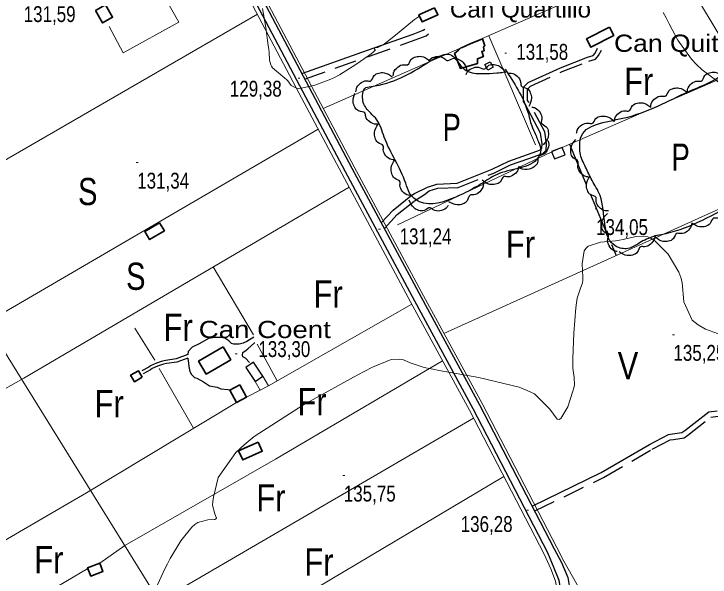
# Model space of a CAD drawing. Extents: x 487425 to 492029, y 4383576 to 4386788.
# Drawn here: x 490517.3 to 490901.3, y 4385154.5 to 4385465.2 of the extents above; entities that cross this region are included whole.
import ezdxf
from ezdxf.enums import TextEntityAlignment as Align

# ---------------------------------------------------------------- set-up
doc = ezdxf.new("R2010")
doc.units = 0
doc.header["$LTSCALE"] = 4
doc.linetypes.add('LONG_DASHED', pattern=[7.5, 6, -1.5])
doc.linetypes.add('MEDIUM_DASHED', pattern=[4.5, 3, -1.5])
for name, color, linetype, lineweight in [('21', 7, 'Continuous', 25), ('25', 7, 'LONG_DASHED', 25), ('27', 7, 'Continuous', 25), ('36', 7, 'Continuous', 25), ('38', 7, 'Continuous', 25), ('47', 7, 'Continuous', 35), ('48', 7, 'MEDIUM_DASHED', 25), ('51', 7, 'Continuous', 13), ('7', 7, 'Continuous', 13), ('9', 7, 'Continuous', 13)]:
    doc.layers.add(name, color=color, linetype=linetype, lineweight=lineweight)
doc.layers.add('31', color=7, linetype='Continuous')
doc.layers.add('5', color=7, linetype='Continuous')

msp = doc.modelspace()

# ---------------------------------------------------------------- linework, layer by layer
at = {"layer": '21'}
for points in [[(490777.11, 4385437.26), (490779.99, 4385438.8), (490781.6, 4385435.75), (490778.72, 4385434.21)], [(490645.16, 4385270.16), (490650.38, 4385262.38), (490654.67, 4385265.26), (490649.45, 4385273.04)]]:
    msp.add_lwpolyline(points, close=True, dxfattribs=at)
at = {"layer": '25'}
msp.add_line((490823.76, 4385393.3), (490849.42, 4385331.9), dxfattribs=at)
at = {"layer": '27'}
for points in [[(490788.2, 4385434.68), (490800.8, 4385410.95), (490802.95, 4385403.52), (490805.03, 4385398.72), (490806.15, 4385395.79), (490807.86, 4385390.98), (490807.17, 4385387.24), (490784.95, 4385377.11), (490776.31, 4385372.26), (490766.4, 4385366.67), (490760.99, 4385364.13), (490741.11, 4385361.57), (490735.58, 4385366.31), (490733.42, 4385371.79), (490721.58, 4385397.17), (490717.41, 4385406.85), (490714.12, 4385410.46), (490710.01, 4385416.25), (490709.65, 4385420.15), (490710.78, 4385424.12), (490714.31, 4385425.16), (490745.02, 4385438.04), (490754.48, 4385442.73), (490756.95, 4385443.02), (490762.71, 4385437.98), (490766.82, 4385434), (490775.97, 4385432.24), (490783.62, 4385432.67), (490787.44, 4385433.03)], [(490726.53, 4385431.01), (490726.76, 4385432.77), (490728.99, 4385435.83), (490732.43, 4385437.18), (490734.48, 4385437.1), (490736.43, 4385440.08), (490739.05, 4385441.52), (490742.06, 4385441.74), (490746.49, 4385439.51)], [(490746.1, 4385439.3), (490747.34, 4385440.58), (490750.96, 4385441.7), (490754.52, 4385440.73), (490756.13, 4385439.45), (490759.47, 4385440.67), (490762.42, 4385440.27), (490764.98, 4385438.64), (490767.2, 4385434.2)], [(490766.79, 4385431.84), (490767.62, 4385433.41), (490770.79, 4385435.49), (490774.48, 4385435.54), (490776.38, 4385434.75), (490779.25, 4385436.85), (490782.21, 4385437.28), (490785.11, 4385436.42), (490788.47, 4385432.78)], [(490705.93, 4385422.18), (490706.18, 4385423.94), (490708.45, 4385426.97), (490711.9, 4385428.28), (490713.96, 4385428.18), (490715.94, 4385431.13), (490718.57, 4385432.54), (490721.59, 4385432.73), (490725.99, 4385430.45)], [(490789.83, 4385432.5), (490791.6, 4385432.54), (490794.97, 4385430.79), (490796.82, 4385427.6), (490797.06, 4385425.56), (490800.3, 4385424.08), (490802.12, 4385421.72), (490802.79, 4385418.77), (490801.26, 4385414.05)], [(490949.83, 4385378.18), (490913.56, 4385359.92), (490874.3, 4385343.32), (490869.57, 4385342.21), (490868.29, 4385341.69), (490864.31, 4385339.98), (490860.41, 4385337.59), (490855.9, 4385335.73), (490849.46, 4385336.95), (490840.62, 4385365.02), (490836.22, 4385373.28), (490832.65, 4385380.64), (490829.6, 4385388.59), (490829.38, 4385392.12), (490829.84, 4385396.62), (490853.2, 4385407.64), (490889.68, 4385422.45), (490901.09, 4385427.52), (490906.95, 4385430.72), (490910.03, 4385432.21), (490917.08, 4385432.34), (490922.9, 4385424.38), (490931.03, 4385409.36), (490939.76, 4385395.98), (490943.49, 4385388.85), (490943.62, 4385381.58), (490945.7, 4385377)], [(490888.75, 4385421.84), (490888.93, 4385423.61), (490891.08, 4385426.73), (490894.48, 4385428.18), (490896.53, 4385428.16), (490898.39, 4385431.19), (490900.97, 4385432.7), (490903.98, 4385433.01), (490908.47, 4385430.9)], [(490718.85, 4385404.53), (490717.1, 4385404.28), (490713.55, 4385405.62), (490711.33, 4385408.57), (490710.85, 4385410.57), (490707.46, 4385411.65), (490705.37, 4385413.78), (490704.35, 4385416.63), (490705.32, 4385421.49)], [(490868.58, 4385413.82), (490868.83, 4385415.57), (490871.11, 4385418.6), (490874.57, 4385419.9), (490876.62, 4385419.8), (490878.62, 4385422.74), (490881.25, 4385424.15), (490884.27, 4385424.32), (490888.67, 4385422.02)], [(490552.62, 4384941.58), (490554.42, 4384943.67), (490554.9, 4384950.57), (490551.02, 4384958.75), (490549.23, 4384963.11), (490546.55, 4384969.04), (490546.27, 4384975.56), (490577.59, 4384991.51), (490608.31, 4385010.39), (490640.99, 4385029.26), (490675.61, 4385047.83), (490715.19, 4385070.58), (490756.65, 4385095.72), (490790.53, 4385116.54), (490822.22, 4385132.71), (490831.7, 4385141.3), (490834.32, 4385140.92), (490836.94, 4385139.04), (490838.42, 4385134.39), (490839.83, 4385127.26), (490841.17, 4385124.33), (490843.93, 4385120.95), (490854.88, 4385120.69), (490881, 4385131.56), (490910.74, 4385145.49), (490944, 4385160.61), (490977.26, 4385174.31), (491011.8, 4385191.9), (491038.91, 4385205.09), (491047.85, 4385210.16), (491048.16, 4385215.03), (491046.15, 4385220.51), (491027.8, 4385249.96), (491013.09, 4385271.3), (490994.07, 4385304.34), (490984.67, 4385319.67), (490979.29, 4385327.18), (490976.61, 4385330.57), (490974.75, 4385335.52), (490975.45, 4385343.54), (490977.85, 4385344.21), (490979.42, 4385344.13), (490980.47, 4385343.6), (490983.46, 4385341.64), (490988.77, 4385336.68), (490990.42, 4385334.95), (490993.78, 4385332.31), (491019.1, 4385348.81), (491045.47, 4385366.05), (491074.68, 4385380.36), (491106.91, 4385400.5), (491123.13, 4385410.28), (491127.87, 4385413.64), (491130.35, 4385415.43), (491144.45, 4385391.54), (491161.89, 4385359.02), (491165.47, 4385353.38)], [(490803.07, 4385413.77), (490804.8, 4385413.34), (490807.58, 4385410.77), (490808.52, 4385407.2), (490808.22, 4385405.17), (490810.94, 4385402.89), (490812.07, 4385400.12), (490811.94, 4385397.1), (490809.22, 4385392.96)], [(490848.44, 4385405.72), (490848.71, 4385407.48), (490851.01, 4385410.5), (490854.47, 4385411.77), (490856.52, 4385411.66), (490858.53, 4385414.6), (490861.17, 4385415.98), (490864.19, 4385416.14), (490868.58, 4385413.82)], [(490827.68, 4385399.38), (490828.06, 4385401.11), (490830.57, 4385403.96), (490834.11, 4385404.99), (490836.15, 4385404.74), (490838.36, 4385407.52), (490841.09, 4385408.72), (490844.11, 4385408.67), (490848.33, 4385406.05)], [(490727.43, 4385384.62), (490725.66, 4385384.79), (490722.53, 4385386.93), (490721.07, 4385390.32), (490721.07, 4385392.37), (490718.03, 4385394.22), (490716.51, 4385396.79), (490716.19, 4385399.79), (490718.27, 4385404.29)], [(490811.82, 4385395.38), (490812.29, 4385393.67), (490811.4, 4385389.98), (490808.74, 4385387.42), (490806.82, 4385386.69), (490806.16, 4385383.2), (490804.3, 4385380.87), (490801.6, 4385379.5), (490796.65, 4385379.86)], [(490834.03, 4385375.25), (490832.29, 4385375.62), (490829.42, 4385378.1), (490828.36, 4385381.64), (490828.61, 4385383.68), (490825.8, 4385385.87), (490824.58, 4385388.59), (490824.61, 4385391.62), (490827.2, 4385395.85)], [(490736.61, 4385364.96), (490734.84, 4385365.13), (490731.7, 4385367.26), (490730.24, 4385370.65), (490730.25, 4385372.7), (490727.21, 4385374.55), (490725.68, 4385377.12), (490725.36, 4385380.12), (490727.44, 4385384.63)], [(490795.79, 4385381.26), (490795.5, 4385379.51), (490793.14, 4385376.53), (490789.66, 4385375.31), (490787.61, 4385375.46), (490785.55, 4385372.56), (490782.88, 4385371.22), (490779.86, 4385371.12), (490775.52, 4385373.51)], [(490845.22, 4385356.48), (490843.44, 4385356.55), (490840.19, 4385358.5), (490838.54, 4385361.8), (490838.42, 4385363.85), (490835.28, 4385365.53), (490833.61, 4385368), (490833.12, 4385370.98), (490834.94, 4385375.59)], [(490776.15, 4385372.17), (490776.12, 4385370.39), (490774.23, 4385367.1), (490770.96, 4385365.39), (490768.91, 4385365.23), (490767.3, 4385362.06), (490764.86, 4385360.34), (490761.89, 4385359.79), (490757.24, 4385361.51)], [(490756.84, 4385359.42), (490755.74, 4385358.02), (490752.24, 4385356.54), (490748.6, 4385357.15), (490746.88, 4385358.27), (490743.68, 4385356.72), (490740.69, 4385356.82), (490737.99, 4385358.18), (490735.34, 4385362.37)], [(490911.02, 4385358.77), (490910.83, 4385357.01), (490908.66, 4385353.9), (490905.25, 4385352.48), (490903.2, 4385352.5), (490901.31, 4385349.49), (490898.73, 4385347.99), (490895.72, 4385347.71), (490891.24, 4385349.84)], [(490850.07, 4385334.07), (490848.36, 4385334.56), (490845.67, 4385337.24), (490844.86, 4385340.84), (490845.24, 4385342.86), (490842.59, 4385345.23), (490841.56, 4385348.04), (490841.8, 4385351.05), (490844.67, 4385355.09)], [(490891.18, 4385349.98), (490890.91, 4385348.22), (490888.59, 4385345.22), (490885.11, 4385343.97), (490883.06, 4385344.1), (490881.03, 4385341.18), (490878.38, 4385339.81), (490875.36, 4385339.67), (490870.99, 4385342.03)], [(490870.79, 4385343.09), (490870.62, 4385341.32), (490868.48, 4385338.19), (490865.08, 4385336.74), (490863.03, 4385336.75), (490861.17, 4385333.71), (490858.61, 4385332.19), (490855.6, 4385331.87), (490851.1, 4385333.97)]]:
    msp.add_spline(points, degree=3, dxfattribs=at)
at = {"layer": '36'}
for points in [[(490586.03, 4385620.72), (490604.02, 4385576.99), (490607.93, 4385561.76), (490612.84, 4385552.24), (490618.34, 4385540.93), (490627.43, 4385524.13), (490649.58, 4385482.52), (490680.08, 4385424.55), (490703.71, 4385380.18), (490741.89, 4385308.92), (490774.19, 4385249.5), (490815.35, 4385170.05), (490819.37, 4385162.64)], [(490582.19, 4385619.14), (490600.07, 4385575.67), (490604.03, 4385560.27), (490609.13, 4385550.38), (490614.65, 4385539.03), (490623.77, 4385522.17), (490645.91, 4385480.58), (490676.41, 4385422.61), (490700.04, 4385378.22), (490738.24, 4385306.94), (490770.52, 4385247.56), (490811.68, 4385168.11), (490815.13, 4385159.68)], [(490819.37, 4385162.64), (490822.86, 4385154.19), (490823.92, 4385147.66), (490822.4, 4385143.3), (490819.81, 4385139.49), (490816.13, 4385135.82), (490810.5, 4385130.98)], [(490815.13, 4385159.68), (490817.83, 4385152.81), (490818.6, 4385148.13), (490817.73, 4385145.64), (490815.81, 4385142.81), (490812.96, 4385139.97), (490809.95, 4385138.25)]]:
    msp.add_lwpolyline(points, dxfattribs=at)
at = {"layer": '38'}
for points in [[(490676.02, 4385432.26), (490712.41, 4385445.14), (490737.53, 4385453.98), (490743.05, 4385456.14), (490744.04, 4385456.85)], [(490738.18, 4385366.1), (490745.52, 4385369.68), (490750.65, 4385371.35), (490761.8, 4385371.76), (490781.07, 4385379.54), (490790.32, 4385384.01), (490800.55, 4385387.66), (490803.18, 4385388.63), (490807.72, 4385390.23), (490808.57, 4385391.06), (490808.77, 4385393.51), (490807.84, 4385399.44), (490799.32, 4385415.34), (490798.35, 4385416.79), (490798.3, 4385424.74), (490800.92, 4385427.35), (490818.74, 4385435.51), (490833.63, 4385441.25), (490836.81, 4385442.32), (490837.88, 4385443.52), (490839.28, 4385446.24)], [(490719.88, 4385349.92), (490726.42, 4385356.99), (490736.27, 4385364.82), (490738.18, 4385366.1)], [(490649.56, 4385286.94), (490645.81, 4385284.55), (490643.7, 4385283.58), (490641.53, 4385283.07), (490640.18, 4385282.99), (490638.53, 4385283), (490637.4, 4385283.3), (490635.83, 4385284.88), (490633.14, 4385286.62), (490630.52, 4385286.77), (490628.12, 4385286.71), (490624.67, 4385286.04), (490619.78, 4385283.36), (490615.58, 4385281.34), (490613.4, 4385278.95), (490613.19, 4385277.22)], [(490647.27, 4385272.93), (490644.95, 4385275.26), (490643.61, 4385276.09), (490643.38, 4385276.99), (490643.61, 4385278.41), (490645.49, 4385279.68), (490646.39, 4385280.35), (490650, 4385283.71), (490650.23, 4385283.79)], [(490613.19, 4385277.22), (490606.75, 4385274.86), (490601.1, 4385273.99), (490599.32, 4385273.6), (490595.96, 4385272.47), (490592.7, 4385271.09), (490591.7, 4385270.39), (490587.83, 4385268.25)], [(490613.16, 4385275.34), (490613.16, 4385275.13), (490613.53, 4385272.5), (490613.75, 4385270.63), (490614.34, 4385267.85), (490615.31, 4385266.35), (490616.95, 4385264.62), (490618.23, 4385264.24), (490621.82, 4385262.13), (490625.19, 4385259.95), (490629.46, 4385259.26), (490631.48, 4385258.43), (490635.23, 4385258.04), (490636.58, 4385257.66)], [(490803.25, 4385193.69), (490841.17, 4385212.14), (490867.89, 4385227.65), (490878.43, 4385233.11), (490880.62, 4385233.46), (490885.81, 4385234.27), (490887.34, 4385235.32), (490900.56, 4385245.62), (490905.29, 4385246.28)]]:
    msp.add_lwpolyline(points, dxfattribs=at)
at = {"layer": '38', "linetype": 'MEDIUM_DASHED'}
for points in [[(490677.61, 4385429.24), (490713.53, 4385441.96), (490738.7, 4385450.82), (490744.68, 4385453.16), (490746.01, 4385454.13)], [(490746.44, 4385367.52), (490751.06, 4385369.02), (490762.3, 4385369.43), (490782.02, 4385377.4), (490791.23, 4385381.85), (490801.34, 4385385.46), (490803.97, 4385386.43), (490808.99, 4385388.19), (490810.83, 4385390), (490811.13, 4385393.6), (490810.09, 4385400.2), (490801.33, 4385416.54), (490800.69, 4385417.51), (490800.64, 4385423.77), (490802.28, 4385425.39), (490819.65, 4385433.35), (490834.42, 4385439.05), (490838.14, 4385440.3), (490839.83, 4385442.18), (490841.37, 4385445.16)], [(490721.63, 4385346.73), (490728.77, 4385354.45), (490738.3, 4385362.03), (490743.72, 4385365.64), (490746.44, 4385367.52)], [(490613.16, 4385275.34), (490607.19, 4385273.15), (490601.42, 4385272.26), (490599.79, 4385271.91), (490596.58, 4385270.83), (490593.56, 4385269.55), (490592.63, 4385268.9), (490588.67, 4385266.72)], [(490804.57, 4385190.98), (490842.59, 4385209.48), (490869.34, 4385225), (490879.39, 4385230.21), (490881.09, 4385230.48), (490886.96, 4385231.4), (490889.13, 4385232.89), (490901.78, 4385242.74), (490905.71, 4385243.3)]]:
    msp.add_lwpolyline(points, dxfattribs=at)
at = {"layer": '38', "linetype": 'LONG_DASHED'}
msp.add_spline([(490856.41, 4385107.49), (490859.65, 4385110.18), (490867.38, 4385114.43), (490873.91, 4385115.53), (490887.03, 4385114.37), (490896.55, 4385115.32), (490924.27, 4385131.13), (490927.87, 4385133.82), (490941.1, 4385145.17), (490947.19, 4385149.8), (490963.04, 4385157.48), (490967.84, 4385158.06), (490984.27, 4385160.94), (490997.92, 4385161.95), (491003.62, 4385163.35), (491033.48, 4385171.21), (491039.72, 4385174.94), (491044.16, 4385180.85), (491046.74, 4385189.62), (491047.5, 4385195.54), (491053.9, 4385202.57), (491077.72, 4385221.09), (491118.14, 4385248.18), (491145.63, 4385263.7), (491161.54, 4385265.75), (491194.04, 4385279.67), (491203.47, 4385287.37)], degree=3, dxfattribs=at)
at = {"layer": '47'}
for points in [[(490562.3, 4385467.01), (490566.18, 4385460.24), (490571.67, 4385463.38), (490567.79, 4385470.15)], [(490749.38, 4385468.61), (490740.69, 4385464.68), (490742.46, 4385460.76), (490751.15, 4385464.69)], [(490845.85, 4385457.83), (490833.22, 4385451.37), (490835.54, 4385446.84), (490848.17, 4385453.3)], [(490775.72, 4385451.37), (490768.89, 4385448.76), (490764.16, 4385446.53), (490763.94, 4385446.6), (490762.51, 4385445.26), (490760.4, 4385443.39), (490763.6, 4385435.13), (490772.98, 4385437.8), (490772.99, 4385440.5), (490776.3, 4385441.69), (490775.4, 4385444.54), (490776.68, 4385444.91), (490776.31, 4385446.86), (490776.69, 4385447.31), (490776.99, 4385447.61)], [(490597.64, 4385350.01), (490589.5, 4385345.12), (490592.14, 4385340.72), (490600.28, 4385345.61)], [(490632.67, 4385281.59), (490619.13, 4385273.63), (490623.33, 4385266.48), (490636.87, 4385274.44)], [(490588.09, 4385264.78), (490583.72, 4385262.25), (490581.64, 4385265.85), (490586.01, 4385268.38)], [(490641.98, 4385260.65), (490645.66, 4385253.84), (490640.08, 4385250.83), (490636.4, 4385257.64)], [(490652.01, 4385228.97), (490641.25, 4385224.15), (490643.51, 4385219.1), (490654.27, 4385223.92)], [(490564.61, 4385162.21), (490557.91, 4385159.69), (490559.64, 4385155.1), (490566.34, 4385157.62)]]:
    msp.add_lwpolyline(points, close=True, dxfattribs=at)
at = {"layer": '48'}
msp.add_lwpolyline([(490819.71, 4385391.55), (490813.9, 4385389.31), (490815.49, 4385385.19), (490821.3, 4385387.43)], close=True, dxfattribs=at)
at = {"layer": '51'}
for p, q in [((490651.65, 4385465), (490463.33, 4385356.18)), ((490779.27, 4385453.14), (490805.09, 4385393.02)), ((490754.5, 4385288.95), (490942.62, 4385374.08)), ((490627.18, 4385325.58), (490649.42, 4385288.07)), ((490584.04, 4385291.86), (490595.01, 4385274.13)), ((490651.5, 4385282.96), (490662.52, 4385262.72)), ((490597.47, 4385269.63), (490616.4, 4385236.6)), ((490654.67, 4385265.26), (490657.73, 4385260)), ((490653.15, 4385257.69), (490645.55, 4385253.79))]:
    msp.add_line(p, q, dxfattribs=at)
for points in [[(490770.28, 4385676.52), (490879.71, 4385498.21), (490946.11, 4385387.72), (490972.53, 4385346.55), (491015.95, 4385275.04), (491056.79, 4385212.45)], [(490587.46, 4385621.31), (490605.49, 4385577.48), (490609.38, 4385562.31), (490614.22, 4385552.93), (490619.71, 4385541.63), (490628.79, 4385524.86), (490650.94, 4385483.24), (490681.44, 4385425.27), (490705.07, 4385380.91), (490743.25, 4385309.65), (490775.55, 4385250.22), (490816.71, 4385170.77), (490820.72, 4385163.37)], [(490580.18, 4385618.32), (490598, 4385574.99), (490601.98, 4385559.5), (490607.19, 4385549.41), (490612.71, 4385538.04), (490621.86, 4385521.14), (490643.99, 4385479.56), (490674.49, 4385421.59), (490698.13, 4385377.2), (490736.33, 4385305.92), (490768.6, 4385246.54), (490809.76, 4385167.09), (490813.48, 4385159.03)], [(490313.87, 4385607.89), (490313.11, 4385605.12), (490313.1, 4385601.75), (490319.28, 4385587.48), (490405.61, 4385447.53), (490502.62, 4385293.98), (490596.94, 4385142.16), (490654.78, 4385048.84)], [(490687.94, 4385413.08), (490781.51, 4385454.12), (490880.25, 4385497.32)], [(490569.78, 4385458.21), (490577.53, 4385443.79), (490608.32, 4385460.72), (490599.82, 4385475.81)], [(490728.93, 4385348.78), (490813.99, 4385389.09), (490819.71, 4385391.55), (490914.01, 4385432.43)], [(490330.32, 4385195.31), (490415.12, 4385244.91), (490500.9, 4385294.14), (490638.8, 4385374.55), (490685.07, 4385401.63), (490685.09, 4385401.69)], [(490336.23, 4385192.21), (490335.64, 4385192.29), (490419.99, 4385241.9), (490422.16, 4385241.22), (490426.19, 4385234.08), (490439.86, 4385217.47), (490522.7, 4385264.23), (490702.19, 4385369.63)], [(490650.38, 4385262.38), (490653.15, 4385257.69), (490657.73, 4385260), (490736.84, 4385304.99)], [(490820.72, 4385163.37), (490845.2, 4385119.74), (490956.54, 4385166.65), (491000.39, 4385185.71), (491050.47, 4385208.05), (491111.7, 4385250.6), (491158.64, 4385275.65), (491185.22, 4385287.95), (491198.66, 4385293.38)], [(490564.61, 4385162.21), (490578.51, 4385171.99), (490661.58, 4385219.5), (490753.78, 4385273.82)], [(490640.08, 4385250.83), (490557.3, 4385201.07), (490388.07, 4385102.53)], [(490770.88, 4385242.15), (490597.31, 4385141.11), (490508.68, 4385088.97), (490429.06, 4385042.42), (490428.53, 4385041.45), (490426.53, 4385039.6)], [(490446.39, 4385007.93), (490448.23, 4385011.4), (490537.91, 4385062.86), (490618.28, 4385109.18), (490787.53, 4385210)], [(490450.92, 4385130.08), (490450.92, 4385132.71), (490484.73, 4385153), (490499.41, 4385124.61), (490558.07, 4385159.26)], [(490813.48, 4385159.03), (490816.11, 4385152.34), (490816.77, 4385148.29), (490816.13, 4385146.44), (490814.44, 4385143.94), (490811.88, 4385141.39), (490809.07, 4385139.78)]]:
    msp.add_lwpolyline(points, dxfattribs=at)
at = {"layer": '7'}
for p, q in [((490788.1, 4385443.45), (490789.1, 4385443.45)), ((490674.09, 4385429.78), (490675.09, 4385429.78)), ((490584.8, 4385383.18), (490585.8, 4385383.18)), ((490837.92, 4385357.6), (490838.92, 4385357.6)), ((490718.45, 4385346.49), (490719.45, 4385346.49)), ((490880.6, 4385288.19), (490881.6, 4385288.19)), ((490639.36, 4385277.6), (490640.36, 4385277.6)), ((490698.77, 4385210.54), (490699.77, 4385210.54)), ((490800.23, 4385191.48), (490801.23, 4385191.48))]:
    msp.add_line(p, q, dxfattribs=at)
at = {"layer": '9'}
for points in [[(490654.36, 4385468.18), (490656.23, 4385457.73), (490657.58, 4385447.85), (490657.83, 4385445.75), (490658.02, 4385443.92), (490658.24, 4385439.62), (490658.92, 4385437.03), (490659.4, 4385436.28), (490660.01, 4385435.52), (490663.26, 4385432.66), (490666.81, 4385429.8), (490667.62, 4385429.03), (490668.34, 4385428.28), (490670.29, 4385425.67), (490673.14, 4385424.16), (490674.43, 4385424.1), (490675.95, 4385424.2), (490683.23, 4385425.84), (490692.02, 4385429.2), (490694.48, 4385430.38), (490696.95, 4385431.66), (490705.95, 4385437.2), (490713.13, 4385442.26), (490714.45, 4385443.23), (490715.48, 4385444.03), (490716.76, 4385445.37), (490716.29, 4385445.6), (490716.21, 4385445.69), (490716.16, 4385445.79), (490716.15, 4385446.25), (490716.51, 4385446.65), (490716.7, 4385446.7), (490716.91, 4385446.74), (490717.99, 4385446.69), (490720.59, 4385447.87), (490721.77, 4385448.69), (490723.14, 4385449.71), (490729.77, 4385455.18), (490738.35, 4385462.03), (490740.95, 4385463.92), (490741.01, 4385463.96)], [(490875.43, 4385465.92), (490877.06, 4385463), (490877.86, 4385461.51), (490878.81, 4385459.72)], [(490878.81, 4385459.72), (490883.5, 4385450.8), (490891.09, 4385440.14), (490893.86, 4385437.25), (490896.93, 4385434.38), (490910.45, 4385424.27)], [(490618.66, 4385184.59), (490624.26, 4385186.08), (490628.16, 4385186.29), (490628.7, 4385186.59), (490628.99, 4385186.99), (490628.09, 4385189.31), (490626.88, 4385194.21), (490626.99, 4385196.23), (490627.3, 4385198.55), (490630, 4385209.36), (490639.62, 4385223.26), (490644.3, 4385227.53), (490649.84, 4385231.98), (490677.1, 4385249.58), (490704.55, 4385264.84), (490710.21, 4385267.81), (490715.03, 4385270.24), (490725.43, 4385274.49), (490730.01, 4385274.66), (490731.16, 4385274.51), (490732.26, 4385274.27), (490735.82, 4385272.72), (490743.6, 4385270.19), (490747.37, 4385269.34), (490751.84, 4385268.42), (490773.79, 4385264.56), (490795.92, 4385259.29), (490800.49, 4385257.48), (490804.39, 4385255.52), (490812.87, 4385247.17), (490816.89, 4385241.68), (490817.98, 4385241.52), (490819.06, 4385241.94), (490822.88, 4385248.39), (490825.69, 4385257.12), (490826.14, 4385258.99), (490826.44, 4385260.62), (490826.31, 4385264.54), (490825.64, 4385269.73), (490825.59, 4385272.17), (490825.6, 4385275.05), (490826.13, 4385289.06), (490827.22, 4385303.04), (490827.58, 4385305.89), (490827.97, 4385308.31), (490829.6, 4385313.38), (490830.88, 4385316.85), (490831.05, 4385318.27), (490831.14, 4385319.88), (490830.8, 4385327.33), (490831.83, 4385334.46), (490832.78, 4385335.87), (490834.02, 4385337.03), (490840.91, 4385339.19), (490849.22, 4385340.03), (490851.36, 4385340.37), (490853.43, 4385340.74), (490860.3, 4385342.47), (490866.94, 4385342.18), (490868.86, 4385341.28), (490870.81, 4385340.04), (490878.14, 4385332.61), (490884.07, 4385322.65), (490885.14, 4385319.82), (490885.95, 4385316.95), (490886.82, 4385306.31), (490891.48, 4385296.21), (490894.69, 4385293.68), (490898.73, 4385291.27), (490920.26, 4385283.55)], [(490595.54, 4385148.28), (490600.46, 4385159.03), (490601.94, 4385161.9), (490603.46, 4385164.73), (490609.36, 4385174.54), (490615.43, 4385182.09), (490617.06, 4385183.49), (490618.66, 4385184.59)]]:
    msp.add_lwpolyline(points, dxfattribs=at)

# ---------------------------------------------------------------- texts
at = {"layer": '31'}
for s, width, p in [('Fr', 0.85, (490861.97, 4385420.49)), ('P', 0.75, (490758.81, 4385395.09)), ('P', 0.75, (490885.1, 4385378.67)), ('S', 0.8, (490558.02, 4385359.72)), ('Fr', 0.85, (490796.7, 4385330.66)), ('S', 0.8, (490584.53, 4385312.97)), ('Fr', 0.85, (490690.61, 4385303.17)), ('Fr', 0.85, (490607.87, 4385284.77)), ('V', 0.85, (490856.05, 4385263.69)), ('Fr', 0.85, (490569.81, 4385242.68)), ('Fr', 0.85, (490681.77, 4385243.79)), ('Fr', 0.85, (490659.04, 4385190.72)), ('Fr', 0.85, (490536.54, 4385156.61)), ('Fr', 0.85, (490685.56, 4385155.34))]:
    msp.add_text(s, height=15, dxfattribs=dict(at, width=width)).set_placement(p, align=Align.CENTER)
at = {"layer": '5'}
for s, width, p in [('Can Quartillo', 1.05, (490757.79, 4385463.17)), ('Can Quitxota', 1.15, (490848.34, 4385444.27)), ('Can Coent', 1.2, (490619.23, 4385286.36))]:
    msp.add_text(s, height=9.5, dxfattribs=dict(at, width=width)).set_placement(p)
at = {"layer": '7', "width": 0.8}
for s, p in [('131,59', (490522.68, 4385460.71)), ('131,58', (490794.41, 4385439.87)), ('129,38', (490636.41, 4385419.56)), ('131,34', (490585.3, 4385368.81)), ('134,05', (490838.42, 4385343.23)), ('131,24', (490730.04, 4385338.13)), ('133,30', (490652.14, 4385275.91)), ('135,25', (490881.1, 4385273.82)), ('135,75', (490699.27, 4385196.17)), ('136,28', (490763.75, 4385179.42))]:
    msp.add_text(s, height=8.75, dxfattribs=at).set_placement(p)

doc.saveas('drawing.dxf')
